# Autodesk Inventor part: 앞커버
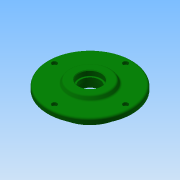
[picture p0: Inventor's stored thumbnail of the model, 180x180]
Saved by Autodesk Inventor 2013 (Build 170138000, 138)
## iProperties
Created: 2016-11
Part Number: 앞커버
Material: 알루미늄 6061
Document SubType Name: Modeling
Designer: mduedu
Density: 2.71 g/cm^3
Mass: 511.35 g
Surface Area: 365.029 cm^2
Volume: 188.69 cm^3
Author: mduedu
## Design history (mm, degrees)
sketch "스케치1"
  geometry: L1 (28.5, -17.5)-(28.5, -30); L2 (28.5, -30)-(22.5, -33.464); L3 (22.5, -33.464)-(22.5, -65); L4 (22.5, -65)-(14.5, -65); L5 (14.5, -65)-(14.5, -47.5); L6 (14.5, -47.5)-(0, -47.5); L7 (0, -47.5)-(0, -23.5); L8 (0, 0)-(28.5, 0); L9 (14.5, -23.5)-(14.5, -15); L10 (14.5, -15)-(20.5, -15); L11 (20.5, -15)-(20.5, -17.5); L12 (0, -23.5)-(14.5, -23.5); L13 (20.5, -17.5)-(28.5, -17.5)
  constraints: 26 end point, 8 parallel, 3 perpendicular, 2 horizontal, 2 vertical alignment, 1 collinear
  dimensions: "d0" = 14.5 distance of L5.end L6.end; "d2" = 8 distance of L3.end L4.end; "d3" = 6 distance between parallel lines of L1 L3; "d4" = 120 deg angle of L3 L2; "d5" = 8 distance of L11.end L1.start; "d6" = 60 diameter of L1.end L8; "d7" = 30 diameter of L10 L8; "d8" = 47 diameter of L12 L8; "d9" = 35 diameter of L13 L8; "d10" = 95 diameter of L6 L8; "d11" = 130 diameter of L4 L8
revolve "회전1" sketch "스케치1" stored, may be unused: angle "d12" = 90 deg
fillet "모깎기1" dims "d13" = 0.5
fillet "모깎기2" dims "d14" = 3
chamfer "모따기1" distance "d15" = 1; stored, may be unused: second distance "d16" = 2, angle "d17" = 45 deg
fillet "모깎기3" dims "d18" = 0.3
sketch "스케치2" dims "d19" = 110
  geometry: 6 further points
  constraints: 2 vertical alignment, 1 coincident, 7 other
  dimensions: "d22" = 360 deg dimension on point (0, 0) point (0, 55) (derived)
sketch "스케치3"
  geometry: 4 further points
  constraints: 4 other
hole "구멍1" sketch "스케치3" at (0, 55), (-55, 0), (55, 0), (0, -55) diameter "d24" = 4.5; stored, may be unused: countersink angle "d28" = 90 deg, drill point angle "d30" = 0 deg; dims "d25" = 6, "d26" = 8, "d27" = 4.6, "d29" = 8
node "솔리드1"
